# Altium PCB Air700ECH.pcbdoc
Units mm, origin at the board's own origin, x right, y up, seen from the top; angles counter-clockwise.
Board outline 24.15 x 27.15 mm, 2 copper layers (Top Layer, Bottom Layer); 1 components, 0 nets, 80 pads, 0 vias.
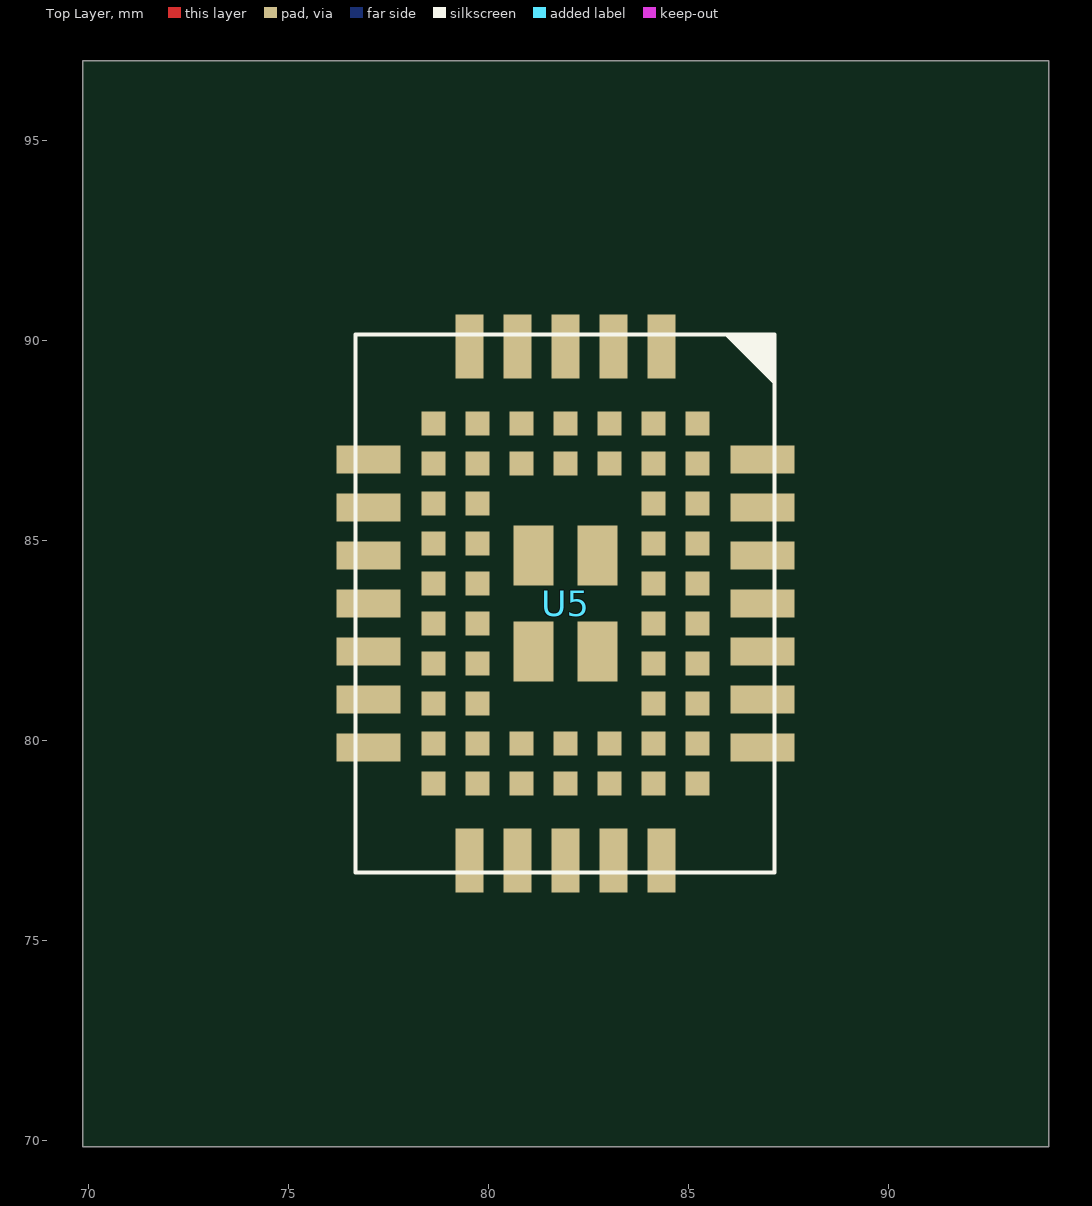
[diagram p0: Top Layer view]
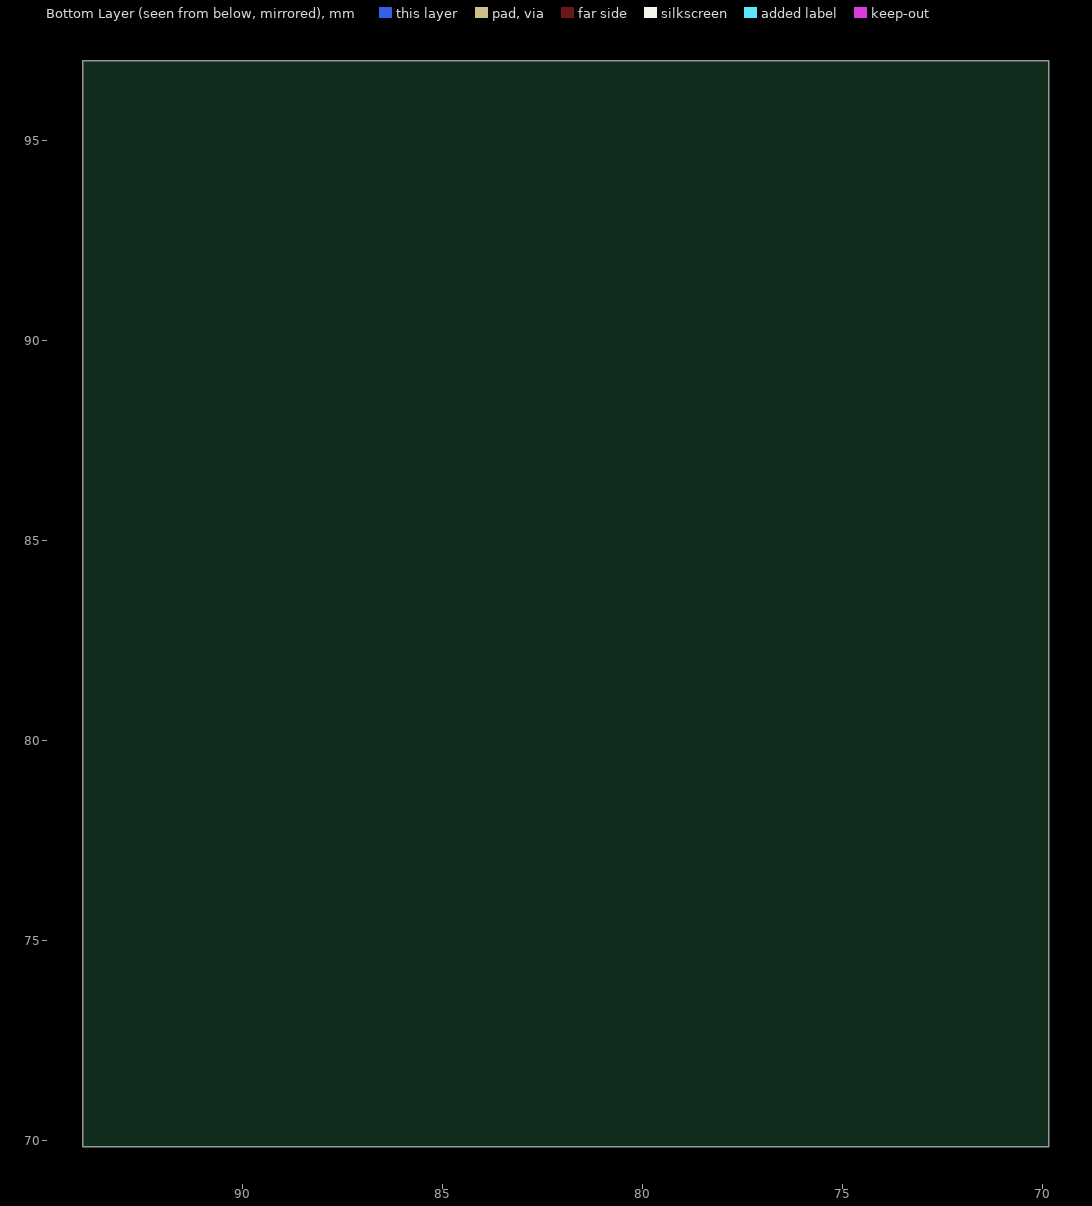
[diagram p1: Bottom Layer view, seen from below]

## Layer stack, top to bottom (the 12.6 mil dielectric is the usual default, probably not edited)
Top Layer: signal copper (thickness not stored)
Dielectric: dielectric 0.32, FR-4, Dk 4.8
Bottom Layer: signal copper (thickness not stored)

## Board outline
94,69.85 69.85,69.85 69.85,97 94,97

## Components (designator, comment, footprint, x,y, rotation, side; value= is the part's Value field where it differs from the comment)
U5 "AIR700ECH@AIR700ECH" AIR700ECH 81.925,83.425 r0 top

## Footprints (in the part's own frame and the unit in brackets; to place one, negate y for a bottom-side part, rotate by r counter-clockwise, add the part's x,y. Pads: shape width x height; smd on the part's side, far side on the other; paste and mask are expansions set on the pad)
AIR700ECH [mm]
  rect 0.7x1.6 smd: 1(2.4,6.425) 2(1.2,6.425) 3(0,6.425) 4(-1.2,6.425) 5(-2.4,6.425) 13(-2.4,-6.425) 14(-1.2,-6.425) 15(0,-6.425) 16(1.2,-6.425) 17(2.4,-6.425)
  rect 1.6x0.7 smd: 6(-4.925,3.6) 7(-4.925,2.4) 8(-4.925,1.2) 9(-4.925,0) 10(-4.925,-1.2) 11(-4.925,-2.4) 12(-4.925,-3.6) 18(4.925,-3.6) 19(4.925,-2.4) 20(4.925,-1.2) 21(4.925,0) 22(4.925,1.2) 23(4.925,2.4) 24(4.925,3.6)
  rect 0.6x0.6 smd: 25(3.3,4.5) 26(2.2,4.5) 27(1.1,4.5) 28(0,4.5) 29(-1.1,4.5) 30(-2.2,4.5) 31(-3.3,4.5) 32(-3.3,3.5) 33(-3.3,2.5) 34(-3.3,1.5) 35(-3.3,0.5) 36(-3.3,-0.5) 37(-3.3,-1.5) 38(-3.3,-2.5) 39(-3.3,-3.5) 40(-3.3,-4.5) 41(-2.2,-4.5) 42(-1.1,-4.5) 43(0,-4.5) 44(1.1,-4.5) 45(2.2,-4.5) 46(3.3,-4.5) 47(3.3,-3.5) 48(3.3,-2.5) 49(3.3,-1.5) 50(3.3,-0.5) 51(3.3,0.5) 52(3.3,1.5) 53(3.3,2.5) 54(3.3,3.5) 55(2.2,3.5) 56(1.1,3.5) 57(0,3.5) 58(-1.1,3.5) 59(-2.2,3.5) 60(-2.2,2.5) 61(-2.2,1.5) 62(-2.2,0.5) 63(-2.2,-0.5) 64(-2.2,-1.5) 65(-2.2,-2.5) 66(-2.2,-3.5) 67(-1.1,-3.5) 68(0,-3.5) 69(1.1,-3.5) 70(2.2,-3.5) 71(2.2,-2.5) 72(2.2,-1.5) 73(2.2,-0.5) 74(2.2,0.5) 75(2.2,1.5) 76(2.2,2.5)
  rect 1x1.5 smd: 77(0.8,1.2) 78(-0.8,1.2) 79(-0.8,-1.2) 80(0.8,-1.2)
  silkscreen extent -5.25,-6.73 5.23,6.73

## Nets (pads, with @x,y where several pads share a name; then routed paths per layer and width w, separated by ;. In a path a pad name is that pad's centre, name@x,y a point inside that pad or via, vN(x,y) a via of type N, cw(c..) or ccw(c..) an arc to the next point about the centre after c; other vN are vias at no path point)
pads on no net: U5.1 U5.2 U5.3 U5.4 U5.5 U5.6 U5.7 U5.8 U5.9 U5.10 U5.11 U5.12 U5.13 U5.14 U5.15 U5.16 U5.17 U5.18 U5.19 U5.20 U5.21 U5.22 U5.23 U5.24 U5.25 U5.26 U5.27 U5.28 U5.29 U5.30 U5.31 U5.32 U5.33 U5.34 U5.35 U5.36 U5.37 U5.38 U5.39 U5.40 U5.41 U5.42 U5.43 U5.44 U5.45 U5.46 U5.47 U5.48 U5.49 U5.50 U5.51 U5.52 U5.53 U5.54 U5.55 U5.56 U5.57 U5.58 U5.59 U5.60 U5.61 U5.62 U5.63 U5.64 U5.65 U5.66 U5.67 U5.68 U5.69 U5.70 U5.71 U5.72 U5.73 U5.74 U5.75 U5.76 U5.77 U5.78 U5.79 U5.80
